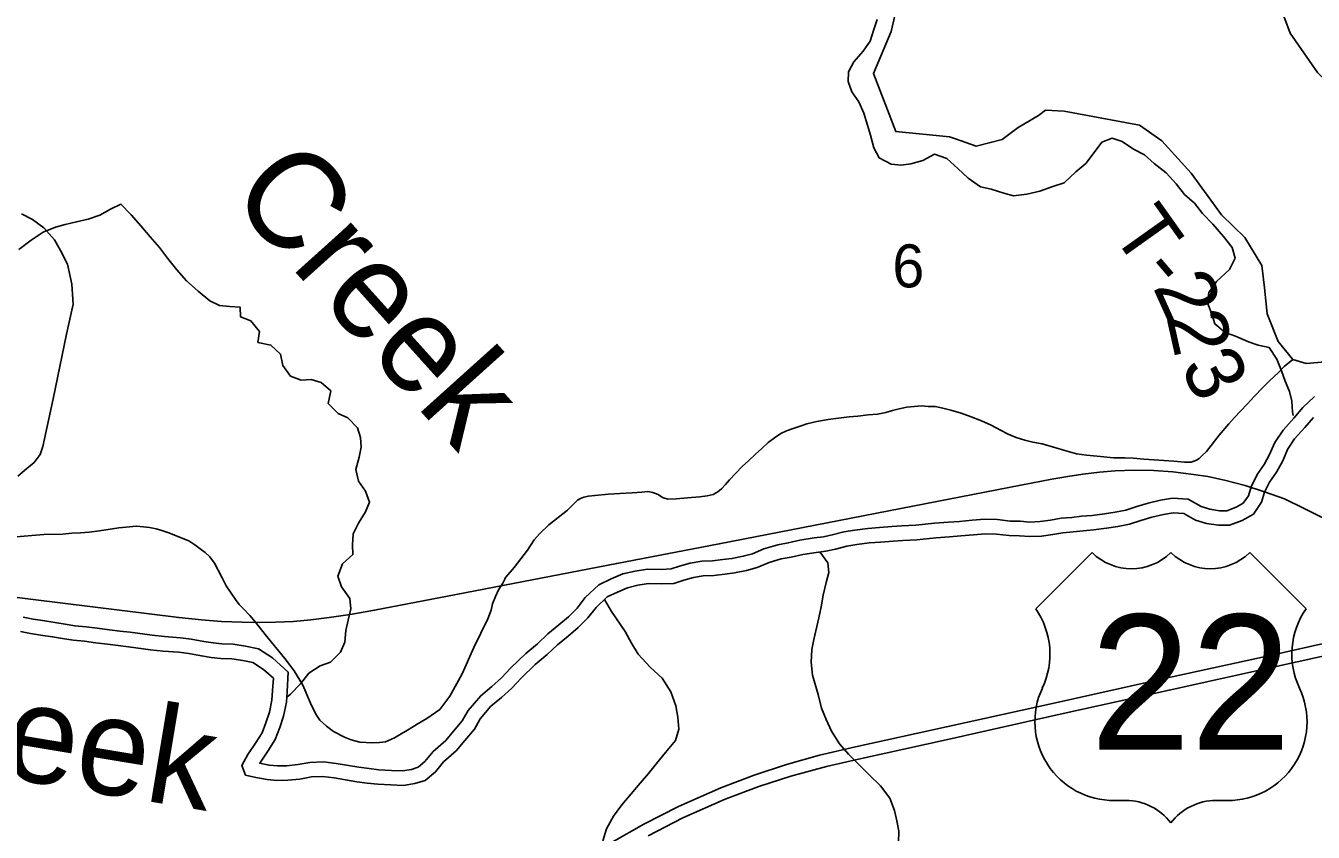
# Model space of a CAD drawing. Extents: x 0 to 34, y 0 to 22.
# Drawn here: x 3.211 to 4.467, y 14.478 to 15.265 of the extents above; entities that cross this region are included whole.
import ezdxf

# ---------------------------------------------------------------- set-up
doc = ezdxf.new("R2010")
doc.units = 0
for name, color, linetype in [('GM_X_Minor_River', 7, 'Continuous'), ('GM_X_Minor_River_Text', 7, 'Continuous'), ('GM_X_Rail_Line', 7, 'Continuous'), ('GM_X_Section_Text', 7, 'Continuous'), ('GM_X_State_Route', 7, 'Continuous'), ('GM_X_Township_Road', 7, 'Continuous'), ('GM_X_Township_Road_Text', 7, 'Continuous'), ('GM_X_US_Location', 7, 'Continuous'), ('GM_X_US_Route', 7, 'Continuous'), ('GM_X_US_Shield', 7, 'Continuous')]:
    doc.layers.add(name, color=color, linetype=linetype)

msp = doc.modelspace()

# ---------------------------------------------------------------- linework, layer by layer
at = {"layer": 'GM_X_Minor_River'}
for points in [[(4.0417, 15.2706), (4.038, 15.2599), (4.0347, 15.2496), (4.0279, 15.2397), (4.0189, 15.2294), (4.0137, 15.2195), (4.0134, 15.21), (4.0169, 15.2001), (4.0238, 15.1903), (4.0285, 15.1793), (4.032, 15.1675), (4.0351, 15.1577), (4.0382, 15.1456), (4.0436, 15.1357), (4.0551, 15.1297), (4.065, 15.1287), (4.0745, 15.1299), (4.0862, 15.133), (4.0976, 15.1392), (4.1094, 15.1351), (4.1201, 15.1253), (4.1304, 15.1159), (4.1423, 15.1076), (4.1529, 15.1051), (4.1651, 15.1014), (4.1746, 15.0988), (4.1875, 15.1004), (4.2001, 15.1032), (4.2129, 15.1078), (4.2239, 15.1113), (4.2352, 15.1221), (4.245, 15.1301), (4.2533, 15.1408), (4.2608, 15.1511), (4.2707, 15.155), (4.2806, 15.1517), (4.2916, 15.1442), (4.3023, 15.1386), (4.3119, 15.1303), (4.3234, 15.1212), (4.3333, 15.1103), (4.3414, 15.1001), (4.351, 15.0914), (4.359, 15.0816), (4.369, 15.0711), (4.3794, 15.059), (4.3878, 15.0484), (4.3906, 15.0378), (4.3853, 15.0267), (4.3725, 15.0152), (4.365, 15.0045), (4.3636, 14.9943), (4.3679, 14.9833), (4.371, 14.9738), (4.3809, 14.9655), (4.3912, 14.9618), (4.4038, 14.9562), (4.4133, 14.9529), (4.424, 14.9507), (4.4313, 14.9393), (4.436, 14.928), (4.4395, 14.9181), (4.4437, 14.9079), (4.4461, 14.8984), (4.4466, 14.8881), (4.4473, 14.8844)], [(3.2044, 15.0465), (3.2165, 15.0554), (3.2282, 15.0631), (3.2403, 15.0681), (3.2498, 15.0708), (3.2608, 15.0732), (3.2722, 15.0759), (3.2836, 15.0798), (3.2938, 15.0856), (3.304, 15.0906), (3.3139, 15.0801), (3.3235, 15.0695), (3.3324, 15.0586), (3.3416, 15.0484), (3.3493, 15.0378), (3.3585, 15.0265), (3.3681, 15.0159), (3.3795, 15.0057), (3.3906, 14.9963), (3.4002, 14.9918), (3.4104, 14.9908), (3.4203, 14.9901), (3.4208, 14.9806), (3.4307, 14.9769), (3.4391, 14.9663), (3.4377, 14.9557), (3.4503, 14.9531), (3.4598, 14.9444), (3.4618, 14.9331), (3.4695, 14.9229), (3.4798, 14.9188), (3.4897, 14.9196), (3.4992, 14.9166), (3.5088, 14.9084), (3.5062, 14.8962), (3.5158, 14.8864), (3.5253, 14.8823), (3.5349, 14.8725), (3.5377, 14.863), (3.5385, 14.8535), (3.5363, 14.844), (3.533, 14.8318), (3.5358, 14.8204), (3.5427, 14.8106), (3.5466, 14.8), (3.5425, 14.7904), (3.5357, 14.7794), (3.5305, 14.7691), (3.5298, 14.7584), (3.5303, 14.7489), (3.5201, 14.7397), (3.5156, 14.7279), (3.5192, 14.7173)], [(4.4681, 14.903), (4.4568, 14.8924), (4.4481, 14.882), (4.4374, 14.8703), (4.4294, 14.858), (4.4243, 14.8464), (4.419, 14.8366), (4.4121, 14.8268), (4.4062, 14.8149), (4.4036, 14.8063), (4.3987, 14.799), (4.3917, 14.795), (4.3826, 14.7916), (4.3756, 14.7916), (4.366, 14.793), (4.3577, 14.7956), (4.3448, 14.8028), (4.3297, 14.8038), (4.318, 14.8019), (4.3058, 14.7989), (4.2948, 14.7957), (4.284, 14.7923), (4.2737, 14.7902), (4.2632, 14.7887), (4.2512, 14.7871), (4.2409, 14.7862), (4.2314, 14.785), (4.2209, 14.7842), (4.2106, 14.7825), (4.2005, 14.781), (4.1906, 14.7806), (4.1812, 14.7813), (4.1713, 14.7815), (4.1591, 14.783), (4.1467, 14.7833), (4.1344, 14.7824), (4.1218, 14.7811)], [(4.1232, 14.767), (4.1357, 14.7682), (4.1471, 14.7691), (4.1581, 14.7688), (4.1703, 14.7674), (4.1805, 14.7671), (4.1904, 14.7664), (4.2018, 14.7669), (4.2128, 14.7685), (4.2227, 14.7701), (4.2329, 14.7709), (4.2424, 14.7721), (4.2526, 14.773), (4.2652, 14.7746), (4.2762, 14.7762), (4.2876, 14.7786), (4.2989, 14.7821), (4.3095, 14.7852), (4.3209, 14.788), (4.3304, 14.7896), (4.3406, 14.7889), (4.3521, 14.7825), (4.3628, 14.7792), (4.3746, 14.7774), (4.3852, 14.7775), (4.3977, 14.7821), (4.4087, 14.7883), (4.4165, 14.8001), (4.4195, 14.8096), (4.4243, 14.8196), (4.4311, 14.8291), (4.4371, 14.8402), (4.4419, 14.8512), (4.4487, 14.8616), (4.4588, 14.8727), (4.4671, 14.8826)], [(4.1218, 14.7811), (4.1111, 14.7803), (4.0976, 14.7794), (4.0792, 14.7774), (4.0657, 14.7769), (4.056, 14.7761), (4.0439, 14.7752), (4.0324, 14.7743), (4.0197, 14.7726), (4.0091, 14.7709), (3.9978, 14.7681), (3.9891, 14.7663), (3.98, 14.7651), (3.9663, 14.763), (3.9549, 14.7602), (3.9446, 14.7585), (3.9311, 14.7545), (3.92, 14.7496), (3.9109, 14.7472), (3.9, 14.745), (3.8912, 14.7439), (3.8811, 14.7427), (3.8705, 14.7423), (3.8593, 14.7404), (3.8489, 14.7374), (3.8407, 14.7348), (3.8313, 14.7344), (3.8175, 14.7347), (3.8055, 14.7328), (3.7936, 14.73), (3.7823, 14.7252), (3.7702, 14.7195), (3.7569, 14.7069), (3.7489, 14.6967), (3.7404, 14.6881), (3.7312, 14.6802), (3.7203, 14.6715), (3.7104, 14.6619), (3.6988, 14.6523), (3.6842, 14.6383), (3.6753, 14.6288), (3.6658, 14.6202), (3.6549, 14.6112), (3.6426, 14.5969), (3.637, 14.5866), (3.6285, 14.5765), (3.6209, 14.5674), (3.6084, 14.5567), (3.6005, 14.5471), (3.5939, 14.5414), (3.5874, 14.5394), (3.5785, 14.5379), (3.5679, 14.5384), (3.5557, 14.5391), (3.5461, 14.5401), (3.5362, 14.5415), (3.5141, 14.5451), (3.5016, 14.5467), (3.4884, 14.5461), (3.4766, 14.5441), (3.466, 14.543), (3.4566, 14.5429), (3.4486, 14.5435), (3.4393, 14.5453), (3.44, 14.5465), (3.4472, 14.5572), (3.4545, 14.5685), (3.4589, 14.5802), (3.4625, 14.5914), (3.4654, 14.6049), (3.4662, 14.6155), (3.4672, 14.6342), (3.4518, 14.6481), (3.4382, 14.6571), (3.4254, 14.6594), (3.4136, 14.6614), (3.4026, 14.6617), (3.394, 14.6627), (3.3849, 14.6641), (3.3727, 14.6663), (3.362, 14.6678), (3.3466, 14.6689), (3.3345, 14.6702), (3.3131, 14.6731), (3.3029, 14.6742), (3.2928, 14.6756), (3.2809, 14.677), (3.2701, 14.6785), (3.2591, 14.6795), (3.2495, 14.6809), (3.2397, 14.6827), (3.2299, 14.6842), (3.2184, 14.6859), (3.2087, 14.6877)], [(3.2061, 14.6737), (3.216, 14.6719), (3.2278, 14.6701), (3.2373, 14.6687), (3.2472, 14.6669), (3.2575, 14.6654), (3.2685, 14.6644), (3.2791, 14.6629), (3.2909, 14.6615), (3.3012, 14.6601), (3.3115, 14.659), (3.3328, 14.6561), (3.3453, 14.6547), (3.3605, 14.6537), (3.3704, 14.6523), (3.3826, 14.6501), (3.3921, 14.6486), (3.4016, 14.6476), (3.4122, 14.6473), (3.4229, 14.6455), (3.4328, 14.6436), (3.4431, 14.6369), (3.4527, 14.6282), (3.452, 14.6164), (3.4513, 14.6069), (3.4488, 14.5951), (3.4454, 14.5848), (3.4417, 14.5749), (3.4354, 14.565), (3.4279, 14.5539), (3.4219, 14.5432), (3.4254, 14.5338), (3.4356, 14.5316), (3.4467, 14.5294), (3.4562, 14.5287), (3.4668, 14.5288), (3.4786, 14.53), (3.49, 14.532), (3.501, 14.5325), (3.512, 14.531), (3.5341, 14.5274), (3.5443, 14.526), (3.5546, 14.5249), (3.5672, 14.5243), (3.5793, 14.5236), (3.5907, 14.5256), (3.6009, 14.5287), (3.6107, 14.5371), (3.6186, 14.5467), (3.6311, 14.5575), (3.6393, 14.5674), (3.6488, 14.5785), (3.6544, 14.5888), (3.6649, 14.601), (3.6751, 14.6095), (3.6853, 14.6187), (3.6943, 14.6283), (3.7082, 14.6417), (3.7199, 14.6513), (3.7297, 14.6608), (3.7403, 14.6693), (3.7501, 14.6777), (3.7595, 14.6873), (3.7674, 14.6972), (3.7783, 14.7076), (3.7882, 14.7122), (3.798, 14.7165), (3.8082, 14.7189), (3.8185, 14.7205), (3.8314, 14.7202), (3.8432, 14.7207), (3.853, 14.7238), (3.8625, 14.7265), (3.872, 14.7281), (3.8822, 14.7286), (3.8929, 14.7298), (3.9024, 14.731), (3.9141, 14.7334), (3.9247, 14.7361), (3.9361, 14.7412), (3.9478, 14.7447), (3.9577, 14.7463), (3.9691, 14.749), (3.982, 14.751), (3.9915, 14.7522), (4.0009, 14.7542), (4.0119, 14.757), (4.0218, 14.7586), (4.0339, 14.7602), (4.0449, 14.761), (4.0571, 14.7619), (4.0666, 14.7627), (4.0803, 14.7632), (4.0989, 14.7653), (4.1121, 14.7661), (4.1232, 14.767)], [(3.9857, 14.7515), (3.9935, 14.7409), (3.9943, 14.7314), (3.9917, 14.7215), (3.9888, 14.7093), (3.987, 14.6979), (3.9848, 14.6872), (3.9797, 14.6659), (3.9778, 14.6564), (3.9772, 14.6438), (3.9784, 14.6313), (3.9839, 14.6123), (3.9874, 14.5991), (3.9917, 14.5881), (3.9971, 14.5767), (4.0048, 14.5643), (4.0137, 14.5541), (4.0336, 14.5345), (4.0447, 14.5232), (4.0539, 14.5114), (4.0586, 14.4993), (4.0609, 14.4891), (4.0626, 14.4792), (4.0623, 14.4682)], [(3.5192, 14.7173), (3.5272, 14.706), (3.5281, 14.6961), (3.5255, 14.685), (3.5233, 14.6748), (3.5223, 14.6634), (3.5182, 14.6538), (3.5084, 14.6439), (3.4985, 14.6404), (3.4872, 14.6331), (3.4793, 14.6227), (3.4695, 14.6128), (3.4658, 14.6097)], [(3.7758, 14.7052), (3.7826, 14.6932), (3.7957, 14.6739), (3.8019, 14.6626), (3.8084, 14.6516), (3.8203, 14.6392), (3.8318, 14.6282), (3.8403, 14.615), (3.8453, 14.6014), (3.8473, 14.5903), (3.8482, 14.5786), (3.8449, 14.5675), (3.8351, 14.556), (3.8264, 14.545), (3.8186, 14.5354), (3.8103, 14.5258), (3.8016, 14.5155), (3.7926, 14.5048), (3.7843, 14.4937), (3.7776, 14.4815), (3.7739, 14.4697)]]:
    msp.add_lwpolyline(points, dxfattribs=at)
at = {"layer": 'GM_X_Rail_Line'}
msp.add_lwpolyline([(4.4787, 14.7833), (4.4588, 14.7935), (4.4387, 14.8032), (4.4193, 14.8102), (4.4004, 14.8162), (4.3805, 14.8213), (4.3641, 14.8249), (4.3501, 14.8271), (4.3299, 14.8297), (4.3115, 14.8308), (4.2923, 14.8311), (4.2737, 14.8304), (4.2585, 14.8291), (4.2422, 14.8274), (4.2274, 14.825), (4.2118, 14.8223), (4.1817, 14.8165), (3.8875, 14.7593), (3.7876, 14.7402), (3.6311, 14.71), (3.5515, 14.6945), (3.5275, 14.6905), (3.507, 14.6875), (3.4893, 14.6853), (3.4723, 14.6837), (3.4548, 14.6828), (3.4389, 14.6827), (3.4224, 14.6828), (3.4022, 14.6837), (3.3827, 14.6853), (3.3604, 14.6875), (3.2186, 14.7051), (2.9988, 14.7325)], dxfattribs=at)
at = {"layer": 'GM_X_State_Route'}
msp.add_lwpolyline([(3.2035, 14.8253), (3.2124, 14.8329), (3.2194, 14.8385), (3.2253, 14.8463), (3.228, 14.8544), (3.2379, 14.9006), (3.251, 14.9638), (3.2574, 14.993), (3.2563, 15.0125), (3.2518, 15.032), (3.245, 15.0454), (3.2393, 15.0559), (3.2287, 15.0675), (3.2178, 15.0755), (3.207, 15.0811)], dxfattribs=at)
at = {"layer": 'GM_X_Township_Road'}
for points in [[(4.5502, 15.1611), (4.5496, 15.1619), (4.4934, 15.1962), (4.4711, 15.219), (4.4444, 15.2572), (4.4269, 15.3047), (4.385, 15.3914), (4.3689, 15.4195), (4.3582, 15.4397), (4.3417, 15.4652), (4.3172, 15.495), (4.2948, 15.5298), (4.2586, 15.6149), (4.235, 15.6314), (4.2175, 15.6447), (4.2125, 15.6544), (4.2131, 15.6659), (4.214, 15.6829), (4.2126, 15.6897)], [(4.1181, 15.1541), (4.112, 15.1562), (4.0597, 15.1614), (4.038, 15.2179), (4.0551, 15.2588), (4.0675, 15.3128), (4.0681, 15.3252)], [(4.447, 14.9391), (4.4328, 14.9565), (4.422, 14.9837), (4.4194, 15.0089), (4.4168, 15.0306), (4.4003, 15.0581), (4.3775, 15.0802), (4.3477, 15.1208), (4.3191, 15.1524), (4.2974, 15.1675), (4.2239, 15.1811), (4.2059, 15.1822), (4.1989, 15.177), (4.1847, 15.1686)], [(4.1847, 15.1686), (4.1791, 15.1653), (4.1636, 15.1535), (4.1382, 15.1472), (4.1181, 15.1541)], [(4.447, 14.9391), (4.4434, 14.936), (4.4384, 14.9321), (4.4329, 14.9264), (4.4241, 14.9182), (4.4173, 14.9116), (4.4096, 14.9033), (4.4023, 14.8954), (4.396, 14.8888), (4.3902, 14.8826), (4.3845, 14.8763), (4.3751, 14.8653), (4.3627, 14.8494), (4.3581, 14.845), (4.3557, 14.8426), (4.3531, 14.8408), (4.3478, 14.8389), (4.3414, 14.8389), (4.3309, 14.8398), (4.3162, 14.8409), (4.3016, 14.842), (4.2913, 14.843), (4.283, 14.8431), (4.272, 14.8431), (4.2594, 14.8444), (4.2456, 14.8459), (4.2359, 14.8472), (4.2247, 14.8503), (4.2159, 14.8531), (4.2025, 14.8567), (4.1933, 14.8586), (4.1856, 14.8604), (4.1772, 14.8631), (4.1695, 14.8664), (4.162, 14.8701), (4.1528, 14.8749), (4.1433, 14.8793), (4.1332, 14.8831), (4.1235, 14.8868), (4.1134, 14.8897), (4.1055, 14.8916), (4.0981, 14.8932), (4.0912, 14.8934), (4.0848, 14.8938), (4.0778, 14.8934), (4.0704, 14.8925), (4.0631, 14.891), (4.0567, 14.8892), (4.0499, 14.8874), (4.042, 14.8859), (4.0328, 14.885), (4.0226, 14.8839), (4.0143, 14.8833), (4.0039, 14.8819), (3.9938, 14.8806), (3.9828, 14.8787), (3.973, 14.8762), (3.9683, 14.8747), (3.9596, 14.8719), (3.953, 14.8694), (3.9477, 14.8668), (3.9415, 14.8626), (3.9354, 14.858), (3.929, 14.8523), (3.923, 14.8468), (3.916, 14.8404), (3.9098, 14.8349), (3.9037, 14.8283), (3.8976, 14.8219), (3.8938, 14.8173), (3.8899, 14.8129), (3.8863, 14.8099), (3.8817, 14.8076), (3.8758, 14.8063), (3.8685, 14.8052), (3.8566, 14.8041), (3.8457, 14.8033), (3.8373, 14.803), (3.8323, 14.8046), (3.8281, 14.8074), (3.8228, 14.8094), (3.818, 14.8103), (3.8122, 14.8098), (3.8028, 14.809), (3.7907, 14.8083), (3.7795, 14.8079), (3.7663, 14.8066), (3.7599, 14.8059), (3.7555, 14.8048), (3.7524, 14.8037), (3.7494, 14.8019), (3.7459, 14.7982), (3.7395, 14.7923), (3.7215, 14.7778), (3.7122, 14.769), (3.7072, 14.7631), (3.7005, 14.7531), (3.6876, 14.7361), (3.6794, 14.7268), (3.6789, 14.7258)], [(4.5674, 14.9167), (4.5601, 14.9253), (4.5535, 14.9308), (4.544, 14.9384), (4.5404, 14.9404), (4.5373, 14.9417), (4.5334, 14.9426), (4.5291, 14.9422), (4.5209, 14.9401), (4.5158, 14.9378), (4.5107, 14.936), (4.5041, 14.9356), (4.4942, 14.9365), (4.4841, 14.9371), (4.4778, 14.9367), (4.4713, 14.9363), (4.46, 14.9352), (4.447, 14.9391)], [(3.6789, 14.7258), (3.6784, 14.7248), (3.6764, 14.721), (3.6724, 14.7144), (3.6695, 14.7081), (3.6665, 14.7008), (3.665, 14.6947), (3.6618, 14.6863), (3.6482, 14.6583), (3.6367, 14.6327), (3.6249, 14.6108), (3.615, 14.5978), (3.6023, 14.5891), (3.5928, 14.5834), (3.5878, 14.5803), (3.5834, 14.5775), (3.5772, 14.5739), (3.5708, 14.5702), (3.562, 14.5664), (3.5563, 14.5656), (3.5495, 14.5652), (3.5371, 14.5659), (3.5286, 14.5681), (3.522, 14.5709), (3.5115, 14.5763), (3.5044, 14.5817), (3.498, 14.5875), (3.4941, 14.5933), (3.4889, 14.6039), (3.4816, 14.6215), (3.4729, 14.6355), (3.4638, 14.6474), (3.4446, 14.6709), (3.4352, 14.683), (3.4297, 14.6896), (3.4236, 14.6958), (3.4194, 14.7001), (3.4158, 14.705), (3.411, 14.7122), (3.4068, 14.7184), (3.4029, 14.7263), (3.3989, 14.7338), (3.3954, 14.7404), (3.3906, 14.7465), (3.3862, 14.7509), (3.3814, 14.7545), (3.3761, 14.7584), (3.3703, 14.7623), (3.3629, 14.7652), (3.3556, 14.7681), (3.3497, 14.7703), (3.344, 14.7722), (3.3383, 14.7738), (3.3319, 14.7751), (3.3259, 14.776), (3.3193, 14.7764), (3.3021, 14.7748), (3.2833, 14.772), (3.273, 14.7707), (3.2646, 14.77), (3.2562, 14.7696), (3.2475, 14.7689), (3.229, 14.7683), (3.198, 14.7657)]]:
    msp.add_lwpolyline(points, dxfattribs=at)
at = {"layer": 'GM_X_US_Route'}
for points in [[(3.783, 14.4683), (3.8139, 14.4859), (3.8477, 14.5033), (3.8891, 14.5215), (3.9217, 14.5338), (3.953, 14.5441), (3.9853, 14.5531), (4.0205, 14.5613), (4.1091, 14.581), (4.2185, 14.605), (4.3219, 14.6279), (4.4248, 14.6506), (4.4927, 14.6658)], [(3.8183, 14.4747), (3.8521, 14.4921), (3.8935, 14.5104), (3.9261, 14.5226), (3.9574, 14.5329), (3.9923, 14.5422), (4.0234, 14.5493), (4.1119, 14.569), (4.2229, 14.5938), (4.3263, 14.6168), (4.4292, 14.6394), (4.4955, 14.6541)]]:
    msp.add_lwpolyline(points, dxfattribs=at)
at = {"layer": 'GM_X_US_Shield'}
for p, q in [((4.2512, 14.7508), (4.1962, 14.6959)), ((4.4599, 14.6959), (4.405, 14.7508)), ((4.2731, 14.5091), (4.2841, 14.5091)), ((4.372, 14.5091), (4.383, 14.5091))]:
    msp.add_line(p, q, dxfattribs=at)
for centre, radius, start, end in [((4.2896, 14.79), 0.0549, 225.573, 314.427), ((4.3665, 14.79), 0.0549, 225.573, 314.427), ((4.1332, 14.6518), 0.0769, 334.5471, 35.0009), ((4.5229, 14.6518), 0.0769, 144.9991, 205.4529), ((4.2723, 14.586), 0.0769, 154.8319, 270.6383), ((4.3839, 14.586), 0.0769, 269.3617, 25.1681), ((4.2841, 14.4542), 0.0549, 36.8699, 90), ((4.372, 14.4542), 0.0549, 90, 143.1301)]:
    msp.add_arc(centre, radius, start, end, dxfattribs=at)

# ---------------------------------------------------------------- texts
at = {"layer": 'GM_X_Minor_River_Text'}
for height, rotation, p in [(0.09469, 311.9835, (3.4074, 15.0983)), (0.0947, 350.5621, (3.0543, 14.5542))]:
    msp.add_text('Creek', height=height, rotation=rotation, dxfattribs=at).set_placement(p)
at = {"layer": 'GM_X_Section_Text'}
msp.add_text('6', height=0.0419, rotation=0, dxfattribs=at).set_placement((4.0564, 15.0094))
at = {"layer": 'GM_X_Township_Road_Text'}
for s, rotation, p in [('T', 305.3972, (4.2691, 15.063)), ('-', 310.6841, (4.2972, 15.0239)), ('2', 294.251, (4.3101, 15.0098)), ('2', 282.649, (4.3235, 14.9808)), ('3', 297.0976, (4.3365, 14.932))]:
    msp.add_text(s, height=0.0568, rotation=rotation, dxfattribs=at).set_placement(p)
at = {"layer": 'GM_X_US_Location'}
for s in ['0', '/']:
    msp.add_text(s, height=0.000189, dxfattribs=at).set_placement((4.328, 14.6234))
msp.add_text('22', height=0.000189, rotation=0, dxfattribs=at).set_placement((4.2889, 14.5842))
at = {"layer": 'GM_X_US_Shield'}
msp.add_text('22', height=0.13184, dxfattribs=at).set_placement((4.2493, 14.5585))

doc.saveas('drawing.dxf')
